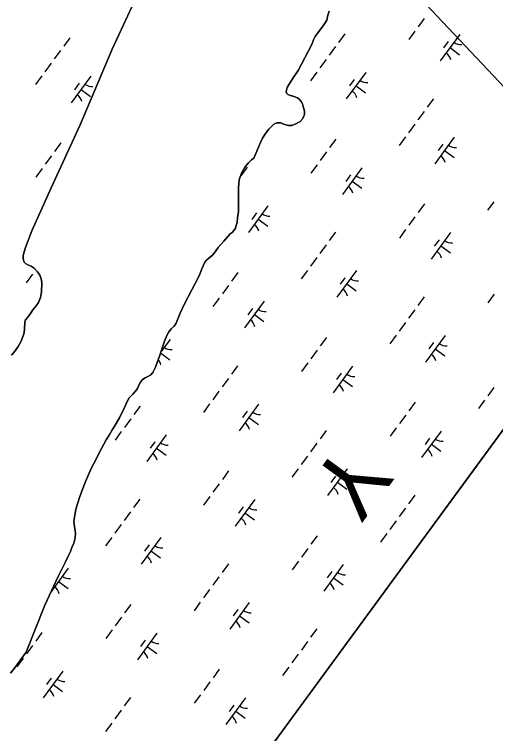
# Model space of a CAD drawing. Extents: x 3905714 to 3926767, y 183354 to 205755.
# Drawn here: x 3918098 to 3918828, y 189073 to 190163 of the extents above; entities that cross this region are included whole.
import ezdxf

# ---------------------------------------------------------------- set-up
doc = ezdxf.new("R2010")
doc.units = 0
for name, color, linetype in [('V-GRID-FRAM', 7, 'Continuous'), ('V-RIVR-IDEN', 7, 'Continuous'), ('V-TOPO-SHOR', 7, 'Continuous'), ('V-UTIL-LINE', 7, 'Continuous'), ('V-WETL-SWMP', 7, 'Continuous')]:
    doc.layers.add(name, color=color, linetype=linetype)

msp = doc.modelspace()

# ---------------------------------------------------------------- linework, layer by layer
at = {"layer": 'V-GRID-FRAM'}
msp.add_lwpolyline([(3924287.8, 196971.1), (3915521.4, 185005.6), (3909313.3, 189695.8), (3918205.9, 201877.9), (3924287.8, 196971.1)], dxfattribs=at)
at = {"layer": 'V-TOPO-SHOR'}
for points in [[(3918197.9, 189996), (3918246.3, 190110.8), (3918283.8, 190191.6)], [(3918536.1, 190023.9), (3918534.9, 190027.9), (3918532.9, 190031.4), (3918531.1, 190034), (3918527.2, 190037), (3918523.3, 190038.6), (3918519.3, 190039.7), (3918515.3, 190040.8), (3918512.6, 190042), (3918510.6, 190044), (3918510.3, 190046.7), (3918511.5, 190052.4), (3918514.8, 190057.8), (3918521.6, 190068.7), (3918528.4, 190078.4), (3918549.2, 190117.9), (3918551.5, 190124.8), (3918554, 190129.8), (3918559.5, 190137.7), (3918563.3, 190142), (3918568.5, 190149.2), (3918571.7, 190154.8), (3918573.5, 190162), (3918575.3, 190168.4)], [(3918183.3, 189349), (3918185.6, 189354.7), (3918188.3, 189361.5), (3918190.3, 189369.4), (3918191, 189376.7), (3918188.9, 189390.2), (3918188.6, 189394.2), (3918188.8, 189397.1), (3918189.3, 189401.6), (3918190.3, 189406.7), (3918191.6, 189413.1), (3918197.3, 189432.5), (3918201.5, 189443.1), (3918203.8, 189448.6), (3918206.7, 189456.3), (3918209.8, 189463.2), (3918215.3, 189475.6), (3918222.1, 189488.8), (3918226.5, 189497.7), (3918230.2, 189505.2), (3918234, 189511.8), (3918237.7, 189518), (3918242, 189525.2), (3918246.1, 189532.4), (3918251, 189540.6), (3918257.5, 189551.7), (3918265.4, 189567.3), (3918270.4, 189578.2), (3918272.4, 189582), (3918275.3, 189585.2), (3918277.7, 189587.3), (3918281.4, 189591.3), (3918284.8, 189596), (3918287.1, 189601), (3918289.6, 189605.9), (3918292.5, 189609.8), (3918296.5, 189612.4), (3918300.8, 189614.2), (3918304.9, 189616.6), (3918308, 189620.5), (3918312.1, 189628.4), (3918315.2, 189637), (3918317.6, 189643.7), (3918325.6, 189667.8), (3918329.6, 189676.6), (3918332.5, 189682.1), (3918334.6, 189684.6), (3918336, 189686.5), (3918340.3, 189690.6), (3918343.3, 189694.9), (3918345.1, 189699.1), (3918347.6, 189705.2), (3918349.7, 189710.3), (3918355.6, 189723.5), (3918379.1, 189767.9), (3918382.6, 189777.3), (3918384.3, 189782.2), (3918387.2, 189787.7), (3918389.5, 189790.6), (3918393.1, 189793.8), (3918398.4, 189798.4), (3918402.7, 189803.3), (3918407.4, 189809.9), (3918415.7, 189819.7), (3918425.4, 189830.4), (3918428.3, 189832.9), (3918430.9, 189835.8), (3918433.3, 189839.1), (3918434.1, 189841.5), (3918435.8, 189847.6), (3918436.6, 189854.8), (3918437.8, 189864.7), (3918437.8, 189893.8), (3918438.1, 189901.5), (3918438.5, 189906.7), (3918439, 189912.3), (3918440.3, 189917), (3918443, 189923.5), (3918447.3, 189930.6), (3918450.2, 189934.6), (3918453.3, 189938.4), (3918457.8, 189942.7), (3918461.2, 189945.6), (3918471.3, 189969), (3918474.2, 189975.9), (3918478.9, 189983), (3918484.1, 189989.2), (3918488.4, 189993.8), (3918491.3, 189996.7), (3918496.3, 189998.8), (3918502.3, 189998.8), (3918505.4, 189997.5), (3918508.3, 189996.4), (3918513.7, 189994.8), (3918519, 189995.1), (3918526, 189997.8), (3918531.4, 190001), (3918535.6, 190005.6), (3918537.8, 190011.5), (3918538.1, 190016.5), (3918536.1, 190023.9)], [(3918094.2, 189646.8), (3918099.4, 189653), (3918104.2, 189659.8), (3918108.6, 189667.9), (3918110.9, 189673.3), (3918112.5, 189678.6), (3918113.5, 189685.6), (3918114, 189697.3), (3918115.3, 189700.1), (3918119, 189704.5), (3918122.7, 189709.7), (3918126.5, 189715.2), (3918131.6, 189721.5), (3918134.8, 189726.5), (3918138, 189734.3), (3918139.3, 189742), (3918139.9, 189756.3), (3918138.9, 189762.2), (3918136.9, 189767.8), (3918133.5, 189773.1), (3918128.5, 189778.7), (3918123.7, 189781.8), (3918118.9, 189783.8), (3918115.4, 189785.4), (3918113.4, 189787.8), (3918111.5, 189792.5), (3918111.8, 189797.8), (3918113.1, 189803.2), (3918115.4, 189810), (3918125, 189835), (3918153.9, 189900.5), (3918197.9, 189996)], [(3918092.3, 189164.5), (3918098.8, 189171.9), (3918116.4, 189196.2), (3918144.3, 189267.4), (3918164.9, 189311.2), (3918176, 189333.4), (3918180.9, 189343.6), (3918183.3, 189349)]]:
    msp.add_lwpolyline(points, dxfattribs=at)
at = {"layer": 'V-UTIL-LINE'}
msp.add_lwpolyline([(3919053.8, 189827.1), (3918313.5, 190612.1), (3918520.5, 191058.3), (3918753.9, 192077.3), (3920478.5, 195285.3), (3921148.4, 196586.7), (3921587.5, 197419.9), (3921944.6, 198057.5)], dxfattribs=at)
at = {"layer": 'V-WETL-SWMP'}
for p, q in [((3918337.9, 188849.9), (3919501.5, 190438.1)), ((3918283.8, 190191.6), (3918246.3, 190110.8)), ((3918575.3, 190168.4), (3918573.5, 190162)), ((3918571.7, 190154.8), (3918568.5, 190149.2)), ((3918573.5, 190162), (3918571.7, 190154.8)), ((3918719.5, 190157.3), (3918710.1, 190144.4)), ((3918568.5, 190149.2), (3918563.3, 190142)), ((3918559.5, 190137.7), (3918554, 190129.8)), ((3918563.3, 190142), (3918559.5, 190137.7)), ((3918599.2, 190133.9), (3918589.7, 190121)), ((3918705.4, 190138), (3918695.9, 190125.1)), ((3918773.4, 190133.1), (3918743.8, 190092.8)), ((3918182.5, 190128.1), (3918173.1, 190115.2)), ((3918551.5, 190124.8), (3918549.2, 190117.9)), ((3918554, 190129.8), (3918551.5, 190124.8)), ((3918755.9, 190122.4), (3918748.8, 190112.7)), ((3918246.3, 190110.8), (3918197.9, 189996)), ((3918549.2, 190117.9), (3918528.4, 190078.4)), ((3918585, 190114.6), (3918575.6, 190101.7)), ((3918758.6, 190113), (3918773.1, 190102.3)), ((3918168.3, 190108.7), (3918158.9, 190095.8)), ((3918154.2, 190089.4), (3918144.7, 190076.5)), ((3918570.8, 190095.2), (3918561.4, 190082.3)), ((3918528.4, 190078.4), (3918521.6, 190068.7)), ((3918140, 190070), (3918130.5, 190057.1)), ((3918214.2, 190069.7), (3918184.6, 190029.4)), ((3918521.6, 190068.7), (3918514.8, 190057.8)), ((3918556.6, 190075.8), (3918547.2, 190062.9)), ((3918630.8, 190075.5), (3918601.3, 190035.2)), ((3918196.7, 190058.9), (3918189.6, 190049.2)), ((3918514.8, 190057.8), (3918511.5, 190052.4)), ((3918613.4, 190064.7), (3918606.3, 190055.1)), ((3918199.4, 190049.5), (3918213.9, 190038.9)), ((3918511.5, 190052.4), (3918510.3, 190046.7)), ((3918510.3, 190046.7), (3918510.6, 190044)), ((3918616.1, 190055.3), (3918630.6, 190044.7)), ((3918510.6, 190044), (3918512.6, 190042)), ((3918512.6, 190042), (3918515.3, 190040.8)), ((3918515.3, 190040.8), (3918523.3, 190038.6)), ((3918523.3, 190038.6), (3918527.2, 190037)), ((3918527.2, 190037), (3918531.1, 190034)), ((3918531.1, 190034), (3918532.9, 190031.4)), ((3918733.4, 190035.6), (3918723.9, 190022.7)), ((3918532.9, 190031.4), (3918534.9, 190027.9)), ((3918534.9, 190027.9), (3918536.1, 190023.9)), ((3918536.1, 190023.9), (3918538.1, 190016.5)), ((3918538.1, 190016.5), (3918537.8, 190011.5)), ((3918719.2, 190016.3), (3918709.7, 190003.4)), ((3918535.6, 190005.6), (3918531.4, 190001)), ((3918537.8, 190011.5), (3918535.6, 190005.6)), ((3918197.9, 189996), (3918153.9, 189900.5)), ((3918488.4, 189993.8), (3918484.1, 189989.2)), ((3918491.3, 189996.7), (3918488.4, 189993.8)), ((3918496.3, 189998.8), (3918491.3, 189996.7)), ((3918502.3, 189998.8), (3918496.3, 189998.8)), ((3918505.4, 189997.5), (3918502.3, 189998.8)), ((3918508.3, 189996.4), (3918505.4, 189997.5)), ((3918513.7, 189994.8), (3918508.3, 189996.4)), ((3918519, 189995.1), (3918513.7, 189994.8)), ((3918526, 189997.8), (3918519, 189995.1)), ((3918531.4, 190001), (3918526, 189997.8)), ((3918705, 189996.9), (3918695.6, 189984)), ((3918478.9, 189983), (3918474.2, 189975.9)), ((3918484.1, 189989.2), (3918478.9, 189983)), ((3918471.3, 189969), (3918461.2, 189945.6)), ((3918474.2, 189975.9), (3918471.3, 189969)), ((3918585.4, 189974.2), (3918576, 189961.3)), ((3918690.8, 189977.5), (3918681.4, 189964.6)), ((3918765, 189977.2), (3918735.5, 189936.9)), ((3918168.7, 189968.4), (3918159.3, 189955.5)), ((3918747.6, 189966.4), (3918740.5, 189956.8)), ((3918154.6, 189949.1), (3918145.1, 189936.2)), ((3918571.2, 189954.9), (3918561.8, 189942)), ((3918750.2, 189957), (3918764.8, 189946.4)), ((3918453.3, 189938.4), (3918450.2, 189934.6)), ((3918457.8, 189942.7), (3918453.3, 189938.4)), ((3918461.2, 189945.6), (3918457.8, 189942.7)), ((3918140.4, 189929.7), (3918130.9, 189916.8)), ((3918450.9, 189931.5), (3918441.4, 189918.6)), ((3918447.3, 189930.6), (3918443, 189923.5)), ((3918450.2, 189934.6), (3918447.3, 189930.6)), ((3918557, 189935.5), (3918547.6, 189922.6)), ((3918625.1, 189930.7), (3918595.5, 189890.4)), ((3918440.3, 189917), (3918439, 189912.3)), ((3918443, 189923.5), (3918440.3, 189917)), ((3918607.6, 189919.9), (3918600.5, 189910.2)), ((3918438.5, 189906.7), (3918438.1, 189901.5)), ((3918439, 189912.3), (3918438.5, 189906.7)), ((3918610.3, 189910.5), (3918624.8, 189899.9)), ((3918153.9, 189900.5), (3918125, 189835)), ((3918438.1, 189901.5), (3918437.8, 189893.8)), ((3918437.8, 189893.8), (3918437.8, 189864.7)), ((3918482.5, 189873.1), (3918453, 189832.7)), ((3918719.6, 189875.9), (3918710.1, 189863)), ((3918825, 189879.2), (3918815.5, 189866.3)), ((3918437.8, 189864.7), (3918436.6, 189854.8)), ((3918465.1, 189862.3), (3918458, 189852.6)), ((3918436.6, 189854.8), (3918435.8, 189847.6)), ((3918467.7, 189852.9), (3918482.3, 189842.3)), ((3918705.4, 189856.6), (3918696, 189843.7)), ((3918433.3, 189839.1), (3918430.9, 189835.8)), ((3918434.1, 189841.5), (3918433.3, 189839.1)), ((3918435.8, 189847.6), (3918434.1, 189841.5)), ((3918125, 189835), (3918115.4, 189810)), ((3918425.4, 189830.4), (3918415.7, 189819.7)), ((3918428.3, 189832.9), (3918425.4, 189830.4)), ((3918430.9, 189835.8), (3918428.3, 189832.9)), ((3918585.1, 189833.2), (3918575.6, 189820.3)), ((3918691.2, 189837.2), (3918681.8, 189824.3)), ((3918759.2, 189832.4), (3918729.7, 189792.1)), ((3918415.7, 189819.7), (3918407.4, 189809.9)), ((3918741.8, 189821.6), (3918734.7, 189811.9)), ((3918115.4, 189810), (3918113.1, 189803.2)), ((3918407.4, 189809.9), (3918402.7, 189803.3)), ((3918570.9, 189813.8), (3918561.4, 189800.9)), ((3918744.5, 189812.2), (3918759, 189801.6)), ((3918111.8, 189797.8), (3918111.5, 189792.5)), ((3918113.1, 189803.2), (3918111.8, 189797.8)), ((3918398.4, 189798.4), (3918393.1, 189793.8)), ((3918402.7, 189803.3), (3918398.4, 189798.4)), ((3918556.7, 189794.5), (3918547.2, 189781.6)), ((3918111.5, 189792.5), (3918113.4, 189787.8)), ((3918113.4, 189787.8), (3918115.4, 189785.4)), ((3918115.4, 189785.4), (3918118.9, 189783.8)), ((3918118.9, 189783.8), (3918123.7, 189781.8)), ((3918387.2, 189787.7), (3918384.3, 189782.2)), ((3918389.5, 189790.6), (3918387.2, 189787.7)), ((3918393.1, 189793.8), (3918389.5, 189790.6)), ((3918123.7, 189781.8), (3918128.5, 189778.7)), ((3918128.5, 189778.7), (3918133.5, 189773.1)), ((3918130.8, 189776), (3918130.6, 189775.7)), ((3918133.5, 189773.1), (3918136.9, 189767.8)), ((3918382.6, 189777.3), (3918379.1, 189767.8)), ((3918384.3, 189782.2), (3918382.6, 189777.3)), ((3918542.5, 189775.1), (3918533.1, 189762.2)), ((3918616.7, 189774.8), (3918587.1, 189734.4)), ((3918125.8, 189769.3), (3918116.4, 189756.4)), ((3918136.9, 189767.8), (3918138.9, 189762.2)), ((3918138.9, 189762.2), (3918139.9, 189756.3)), ((3918379.1, 189767.8), (3918355.6, 189723.5)), ((3918437.1, 189771.8), (3918427.6, 189758.9)), ((3918599.2, 189764), (3918592.1, 189754.3)), ((3918139.9, 189756.3), (3918139.3, 189742)), ((3918422.9, 189752.4), (3918413.5, 189739.5)), ((3918601.9, 189754.6), (3918616.4, 189744)), ((3918139.3, 189742), (3918138, 189734.3)), ((3918138, 189734.3), (3918134.8, 189726.5)), ((3918408.7, 189733.1), (3918399.3, 189720.2)), ((3918719.2, 189734.9), (3918709.8, 189722)), ((3918825.4, 189738.9), (3918815.9, 189726)), ((3918131.6, 189721.5), (3918126.5, 189715.2)), ((3918134.8, 189726.5), (3918131.6, 189721.5)), ((3918355.6, 189723.5), (3918349.7, 189710.3)), ((3918476.7, 189728.3), (3918447.2, 189687.9)), ((3918122.7, 189709.7), (3918119, 189704.5)), ((3918126.5, 189715.2), (3918122.7, 189709.7)), ((3918349.7, 189710.3), (3918347.6, 189705.2)), ((3918459.3, 189717.5), (3918452.2, 189707.8)), ((3918462, 189708.1), (3918476.5, 189697.5)), ((3918705.1, 189715.5), (3918695.6, 189702.6)), ((3918114, 189697.3), (3918113.5, 189685.6)), ((3918115.3, 189700.1), (3918114, 189697.3)), ((3918119, 189704.5), (3918115.3, 189700.1)), ((3918345.1, 189699.1), (3918343.3, 189694.9)), ((3918347.6, 189705.2), (3918345.1, 189699.1)), ((3918690.9, 189696.2), (3918681.4, 189683.2)), ((3918113.5, 189685.6), (3918112.5, 189678.6)), ((3918336, 189686.5), (3918334.6, 189684.6)), ((3918340.3, 189690.6), (3918336, 189686.5)), ((3918343.3, 189694.9), (3918340.3, 189690.6)), ((3918112.5, 189678.6), (3918110.9, 189673.3)), ((3918329.6, 189676.6), (3918325.6, 189667.8)), ((3918332.5, 189682.1), (3918329.6, 189676.6)), ((3918334.6, 189684.6), (3918332.5, 189682.1)), ((3918676.7, 189676.8), (3918667.2, 189663.9)), ((3918750.9, 189676.5), (3918721.3, 189636.1)), ((3918108.6, 189667.9), (3918104.2, 189659.8)), ((3918110.9, 189673.3), (3918108.6, 189667.9)), ((3918325.6, 189667.8), (3918317.6, 189643.7)), ((3918334.2, 189670.6), (3918320.2, 189651.5)), ((3918571.3, 189673.5), (3918561.8, 189660.6)), ((3918733.4, 189665.7), (3918726.3, 189656)), ((3918099.4, 189653), (3918094.2, 189646.8)), ((3918104.2, 189659.8), (3918099.4, 189653)), ((3918557.1, 189654.1), (3918547.6, 189641.2)), ((3918736.1, 189656.3), (3918750.6, 189645.7)), ((3918317.6, 189643.7), (3918315.2, 189637)), ((3918319.8, 189650.2), (3918333.9, 189639.8)), ((3918315.2, 189637), (3918312.1, 189628.4)), ((3918436.7, 189630.7), (3918427.3, 189617.8)), ((3918542.9, 189634.8), (3918533.5, 189621.9)), ((3918308, 189620.5), (3918304.9, 189616.6)), ((3918312.1, 189628.4), (3918308, 189620.5)), ((3918610.9, 189630), (3918581.4, 189589.6)), ((3918292.5, 189609.8), (3918289.6, 189605.9)), ((3918296.5, 189612.4), (3918292.5, 189609.8)), ((3918300.8, 189614.2), (3918296.5, 189612.4)), ((3918304.9, 189616.6), (3918300.8, 189614.2)), ((3918422.6, 189611.4), (3918413.1, 189598.5)), ((3918593.5, 189619.2), (3918586.4, 189609.5)), ((3918596.1, 189609.8), (3918610.7, 189599.1)), ((3918287.1, 189601), (3918284.8, 189596)), ((3918289.6, 189605.9), (3918287.1, 189601)), ((3918825.1, 189597.8), (3918815.6, 189584.9)), ((3918277.7, 189587.3), (3918275.3, 189585.2)), ((3918281.4, 189591.3), (3918277.7, 189587.3)), ((3918284.8, 189596), (3918281.4, 189591.3)), ((3918408.4, 189592), (3918398.9, 189579.1)), ((3918270.4, 189578.2), (3918265.4, 189567.3)), ((3918272.4, 189582), (3918270.4, 189578.2)), ((3918275.3, 189585.2), (3918272.4, 189582)), ((3918810.9, 189578.5), (3918801.4, 189565.6)), ((3918265.4, 189567.3), (3918257.5, 189551.7)), ((3918288.8, 189569.4), (3918279.3, 189556.5)), ((3918394.2, 189572.7), (3918384.7, 189559.8)), ((3918468.4, 189572.3), (3918438.8, 189532)), ((3918705.5, 189575.2), (3918696, 189562.3)), ((3918450.9, 189561.6), (3918443.8, 189551.9)), ((3918691.3, 189555.8), (3918681.8, 189542.9)), ((3918257.5, 189551.7), (3918251, 189540.6)), ((3918274.6, 189550), (3918265.1, 189537.1)), ((3918453.6, 189552.2), (3918468.1, 189541.5)), ((3918246.1, 189532.4), (3918242, 189525.2)), ((3918251, 189540.6), (3918246.1, 189532.4)), ((3918570.9, 189532.4), (3918561.5, 189519.5)), ((3918677.1, 189536.5), (3918667.6, 189523.6)), ((3918242, 189525.2), (3918237.7, 189518)), ((3918260.4, 189530.7), (3918251, 189517.7)), ((3918328.4, 189525.8), (3918298.9, 189485.5)), ((3918745.1, 189531.6), (3918715.5, 189491.3)), ((3918234, 189511.8), (3918230.2, 189505.2)), ((3918237.7, 189518), (3918234, 189511.8)), ((3918311, 189515.1), (3918303.9, 189505.4)), ((3918556.7, 189513.1), (3918547.3, 189500.2)), ((3918727.6, 189520.9), (3918720.6, 189511.2)), ((3918730.3, 189511.5), (3918744.8, 189500.8)), ((3918230.2, 189505.2), (3918222.1, 189488.8)), ((3918313.6, 189505.7), (3918328.2, 189495)), ((3918222.1, 189488.8), (3918215.3, 189475.6)), ((3918542.6, 189493.7), (3918533.1, 189480.8)), ((3918215.3, 189475.6), (3918209.8, 189463.2)), ((3918423, 189471.1), (3918413.5, 189458.2)), ((3918528.4, 189474.4), (3918518.9, 189461.5)), ((3918602.6, 189474), (3918573, 189433.7)), ((3918206.7, 189456.3), (3918203.8, 189448.6)), ((3918209.8, 189463.2), (3918206.7, 189456.3)), ((3918585.1, 189463.3), (3918578, 189453.6)), ((3918203.8, 189448.6), (3918201.5, 189443.1)), ((3918408.8, 189451.7), (3918399.3, 189438.8)), ((3918587.8, 189453.9), (3918602.3, 189443.2)), ((3918201.5, 189443.1), (3918197.3, 189432.5)), ((3918705.1, 189434.1), (3918695.7, 189421.2)), ((3918197.3, 189432.5), (3918191.7, 189413.1)), ((3918288.4, 189428.3), (3918279, 189415.4)), ((3918394.6, 189432.3), (3918385.1, 189419.4)), ((3918462.6, 189427.5), (3918433.1, 189387.2)), ((3918191.7, 189413.1), (3918190.3, 189406.7)), ((3918445.2, 189416.7), (3918438.1, 189407.1)), ((3918690.9, 189414.8), (3918681.5, 189401.9)), ((3918189.3, 189401.6), (3918188.8, 189397.1)), ((3918190.3, 189406.7), (3918189.3, 189401.6)), ((3918274.2, 189408.9), (3918264.8, 189396)), ((3918447.8, 189407.3), (3918462.3, 189396.7)), ((3918188.8, 189397.1), (3918188.6, 189394.2)), ((3918188.6, 189394.2), (3918188.9, 189390.2)), ((3918676.7, 189395.4), (3918667.3, 189382.5)), ((3918188.9, 189390.2), (3918191, 189376.7)), ((3918260.1, 189389.6), (3918250.6, 189376.7)), ((3918190.3, 189369.4), (3918188.3, 189361.5)), ((3918191, 189376.7), (3918190.3, 189369.4)), ((3918245.9, 189370.2), (3918236.4, 189357.3)), ((3918320.1, 189369.9), (3918290.5, 189329.6)), ((3918557.1, 189372.8), (3918547.7, 189359.9)), ((3918662.6, 189376.1), (3918653.1, 189363.1)), ((3918188.3, 189361.5), (3918185.6, 189354.7)), ((3918302.6, 189359.1), (3918295.5, 189349.5)), ((3918183.3, 189349), (3918180.9, 189343.6)), ((3918185.6, 189354.7), (3918183.3, 189349)), ((3918305.3, 189349.7), (3918319.8, 189339.1)), ((3918543, 189353.4), (3918533.5, 189340.5)), ((3918180.9, 189343.6), (3918176, 189333.4)), ((3918176, 189333.4), (3918164.9, 189311.2)), ((3918422.6, 189330), (3918413.2, 189317.1)), ((3918528.8, 189334), (3918519.3, 189321.1)), ((3918596.8, 189329.2), (3918567.2, 189288.9)), ((3918180.1, 189323.4), (3918153.6, 189287.1)), ((3918579.3, 189318.4), (3918572.2, 189308.8)), ((3918164.9, 189311.2), (3918144.3, 189267.4)), ((3918165.3, 189303.2), (3918179.9, 189292.6)), ((3918408.4, 189310.6), (3918399, 189297.7)), ((3918582, 189309), (3918596.5, 189298.4)), ((3918394.2, 189291.3), (3918384.8, 189278.4)), ((3918380.1, 189271.9), (3918370.6, 189259)), ((3918454.2, 189271.6), (3918424.7, 189231.3)), ((3918144.3, 189267.4), (3918116.4, 189196.2)), ((3918274.6, 189268.6), (3918265.2, 189255.7)), ((3918436.8, 189260.8), (3918429.7, 189251.1)), ((3918260.5, 189249.3), (3918251, 189236.4)), ((3918439.5, 189251.4), (3918454, 189240.8)), ((3918246.3, 189229.9), (3918236.8, 189217)), ((3918556.8, 189231.7), (3918547.3, 189218.8)), ((3918140.1, 189225.9), (3918130.7, 189213)), ((3918314.3, 189225.1), (3918284.7, 189184.7)), ((3918125.9, 189206.5), (3918116.5, 189193.6)), ((3918296.8, 189214.3), (3918289.7, 189204.6)), ((3918542.6, 189212.3), (3918533.2, 189199.4)), ((3918116.4, 189196.2), (3918098.8, 189171.9)), ((3918299.5, 189204.9), (3918314, 189194.3)), ((3918111.8, 189187.1), (3918102.3, 189174.2)), ((3918528.4, 189193), (3918519, 189180.1)), ((3918514.2, 189173.6), (3918504.8, 189160.7)), ((3918098.8, 189171.9), (3918092.3, 189164.5)), ((3918171.7, 189167.5), (3918142.2, 189127.1)), ((3918408.8, 189170.3), (3918399.4, 189157.4)), ((3918154.3, 189156.7), (3918147.2, 189147)), ((3918394.6, 189151), (3918385.2, 189138.1)), ((3918157, 189147.3), (3918171.5, 189136.7)), ((3918380.5, 189131.6), (3918371, 189118.7)), ((3918274.3, 189127.6), (3918264.8, 189114.7)), ((3918448.5, 189126.8), (3918418.9, 189086.4)), ((3918260.1, 189108.2), (3918250.7, 189095.3)), ((3918431, 189116), (3918423.9, 189106.3)), ((3918433.7, 189106.6), (3918448.2, 189096)), ((3918245.9, 189088.8), (3918236.5, 189075.9))]:
    msp.add_line(p, q, dxfattribs=at)
for centre, start, end in [((3918775.1, 190135.1), 233, 274.5436), ((3918742.5, 190090.5), 13, 54.5436), ((3918215.9, 190071.7), 233, 274.5436), ((3918632.6, 190077.5), 233, 274.5436), ((3918599.9, 190032.9), 13, 54.5436), ((3918183.2, 190027.1), 13, 54.5436), ((3918766.7, 189979.2), 233, 274.5436), ((3918734.1, 189934.6), 13, 54.5436), ((3918626.8, 189932.7), 233, 274.5436), ((3918594.1, 189888.1), 13, 54.5436), ((3918484.3, 189875.1), 233, 274.5436), ((3918451.6, 189830.5), 13, 54.5436), ((3918761, 189834.4), 233, 274.5436), ((3918728.3, 189789.8), 13, 54.5436), ((3918618.4, 189776.7), 233, 274.5436), ((3918585.8, 189732.2), 13, 54.5436), ((3918478.5, 189730.2), 233, 274.5436), ((3918445.8, 189685.7), 13, 54.5436), ((3918752.6, 189678.4), 233, 274.5436), ((3918335.9, 189672.6), 233, 274.5436), ((3918720, 189633.9), 13, 54.5436), ((3918303.3, 189628.1), 13, 42.5526), ((3918612.7, 189631.9), 233, 274.5436), ((3918580, 189587.4), 13, 54.5436), ((3918470.1, 189574.3), 233, 274.5436), ((3918437.5, 189529.7), 13, 54.5436), ((3918330.2, 189527.8), 233, 274.5436), ((3918746.8, 189533.6), 233, 274.5436), ((3918714.2, 189489.1), 13, 54.5436), ((3918297.5, 189483.2), 13, 54.5436), ((3918604.3, 189476), 233, 274.5436), ((3918571.7, 189431.4), 13, 54.5436), ((3918464.3, 189429.5), 233, 274.5436), ((3918431.7, 189384.9), 13, 54.5436), ((3918321.8, 189371.9), 233, 274.5436), ((3918289.2, 189327.3), 13, 54.5436), ((3918598.5, 189331.2), 233, 274.5436), ((3918181.9, 189325.4), 233, 274.5436), ((3918149.2, 189280.8), 13, 54.5436), ((3918565.9, 189286.6), 13, 54.5436), ((3918456, 189273.6), 233, 274.5436), ((3918423.3, 189229), 13, 54.5436), ((3918316, 189227.1), 233, 274.5436), ((3918283.4, 189182.5), 13, 54.5436), ((3918173.5, 189169.4), 233, 274.5436), ((3918140.8, 189124.9), 13, 54.5436), ((3918450.2, 189128.7), 233, 274.5436), ((3918417.6, 189084.2), 13, 54.5436)]:
    msp.add_arc(centre, 17.6, start, end, dxfattribs=at)

# ---------------------------------------------------------------- texts
at = {"layer": 'V-RIVR-IDEN'}
msp.add_text('Y', height=100, rotation=233.8714, dxfattribs=at).set_placement((3918595.2, 189520.4))

doc.saveas('drawing.dxf')
